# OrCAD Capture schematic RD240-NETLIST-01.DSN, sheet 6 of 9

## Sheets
6 4: size A3
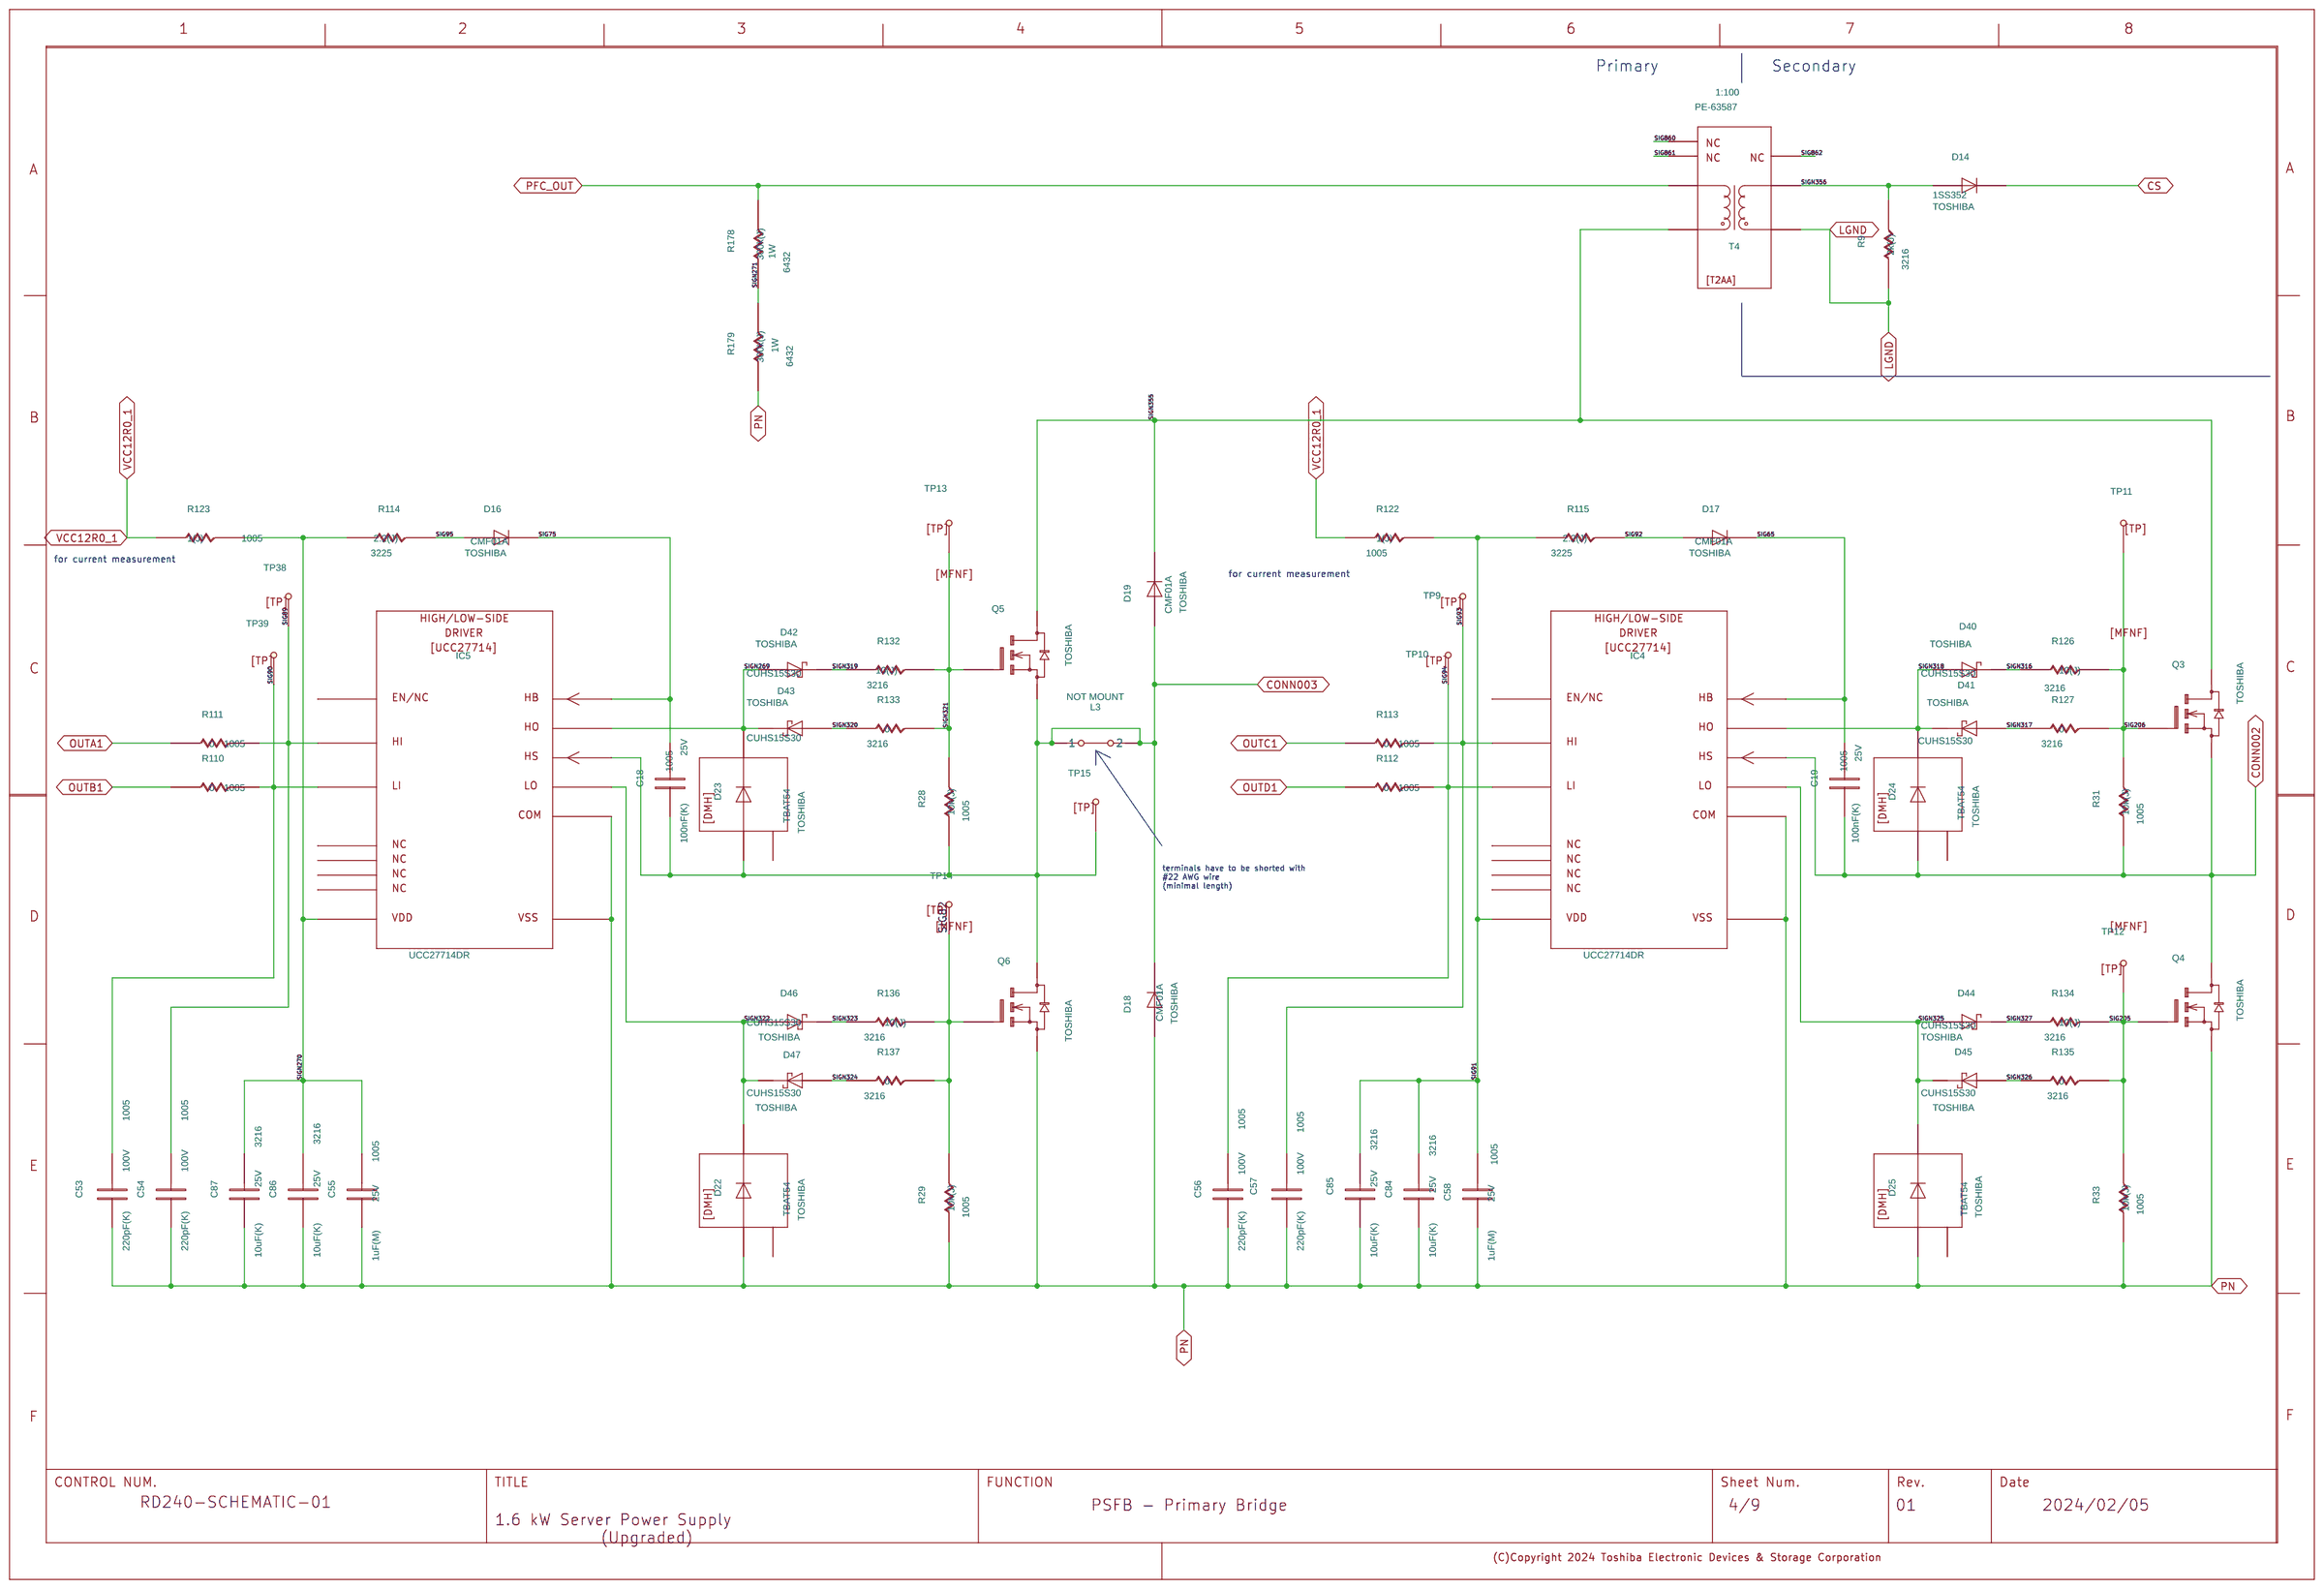
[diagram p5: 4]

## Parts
C18  C
C19  C
C53  C
C54  C
C55  C
C56  C
C57  C
C58  C
C84  C
C85  C
C86  C
C87  C
D14  D
D16  D
D17  D
D18  D
D19  D
D22  DMH
D23  DMH
D24  DMH
D25  DMH
D40  CUHS15S30
D41  CUHS15S30
D42  CUHS15S30
D43  CUHS15S30
D44  CUHS15S30
D45  CUHS15S30
D46  CUHS15S30
D47  CUHS15S30
IC4  L27714
IC5  L27714
L3  JP
Q3  TK095N65Z5
Q4  TK095N65Z5
Q5  TK095N65Z5
Q6  TK095N65Z5
R9  R
R28  R
R29  R
R31  R
R33  R
R110  R
R111  R
R112  R
R113  R
R114  R
R115  R
R122  R
R123  R
R126  R
R127  R
R132  R
R133  R
R134  R
R135  R
R136  R
R137  R
R178  R
R179  R
T4  T2AA
TP9  TP
TP10  TP
TP11  TP
TP12  TP
TP13  TP
TP14  TP
TP15  TP
TP38  TP
TP39  TP
U?#5  WAKU_DEF100

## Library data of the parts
C18 = C: ADSCNVFLAG: ON; ADSCOMPONENTNAME: C_1005; ADSMODELNAME: s_C1005JB1C224KT; AUTHOR: sptcae13; CAPACITANCETOLE: K; CDMASTERCADCELG: KC0005; CHIPSIZE: 1005; COMP: PRT_52; COMPONENTTYPE: 4; DATE: 2024/01/31; FNLEADFREETHET1GT2GMCTH1: N_N_N; GCOUNT: 1; ICX_PART_MODEL: CON_220N; INSTANCENAME: cmp63; MAKER: TDK; MAXGCOUNT: 1; NOMINALCAPACITA: 220n; OUMECLASSIFICATION: ƒZƒ‰ƒ~ƒbƒNƒRƒ“ƒfƒ“ƒT; OUMEMAKER: TDK ‚s‚c‚j; OUMEMAKERKATAMEI: C1005JB1C224KT; QUADMODEL: CON_220N; RATEDVOLTAGE: 16; SAVECOUNT: 0; SIZECODESMD: 1005; SQ_PART_MODEL: CON_220N; TEMPCHARACTERI2: B; TIME: 13:58:26; UPDATEDATE: 2024/01/31; UPDATETIME: 13:58:26; UPDATEUSER: sptcae13; VAL1: 100nF(K); VAL2: 25V; VAL3: C1005X7R1E104K050BB
C19 = C: ADSMODELNAME: s_C1005JB1C224KT; AUTHOR: sptcae13; CAPACITANCETOLE: K; CDMASTERCADCELG: KC0005; CHIPSIZE: 1005; COMP: PRT_52; COMPONENTTYPE: 4; DATE: 2024/01/31; FNLEADFREETHET1GT2GMCTH1: N_N_N; GCOUNT: 1; INSTANCENAME: cmp58; MAKER: TDK; MAXGCOUNT: 1; NOMINALCAPACITA: 220n; OUMECLASSIFICATION: ƒZƒ‰ƒ~ƒbƒNƒRƒ“ƒfƒ“ƒT; OUMEMAKER: TDK ‚s‚c‚j; OUMEMAKERKATAMEI: C1005JB1C224KT; QUADMODEL: CON_220N; RATEDVOLTAGE: 16; SAVECOUNT: 0; SIZECODESMD: 1005; TEMPCHARACTERI2: B; TIME: 13:58:26; UPDATEDATE: 2024/01/31; UPDATETIME: 13:58:26; UPDATEUSER: sptcae13; VAL1: 100nF(K); VAL2: 25V; VAL3: C1005X7R1E104K050BB
C53 = C: ADSMODELNAME: s_GRM155R61A225KE95D; AUTHOR: sptcae13; CAPACITANCETOLE: K; CDMASTERCADCELG: KC0005; CHIPSIZE: 1005; COMP: PRT_52; COMPONENTTYPE: 4; DATE: 2024/01/31; FNLEADFREETHET1GT2GMCTH1: N_N_N; GCOUNT: 1; INSTANCENAME: cmp165; MAKER: TDK; MAXGCOUNT: 1; NOMINALCAPACITA: 2.2u; OUMECLASSIFICATION: ƒZƒ‰ƒ~ƒbƒNƒRƒ“ƒfƒ“ƒT; OUMEMAKER: MRT ºc»ì; OUMEMAKERKATAMEI: GRM155R61A225KE95D; PMPRODUCTSTYPEG: HD1; QUADMODEL: CON_2.2U; RATEDVOLTAGE: 10; SAVECOUNT: 0; SIZECODESMD: 1005; TIME: 13:58:26; UPDATEDATE: 2024/01/31; UPDATETIME: 13:58:26; UPDATEUSER: sptcae13; VAL1: 220pF(K); VAL2: 100V; VAL3: GRM155R72A221KA01
C54 = C: ADSMODELNAME: s_GRM155R61A225KE95D; AUTHOR: sptcae13; CAPACITANCETOLE: K; CDMASTERCADCELG: KC0005; CHIPSIZE: 1005; COMP: PRT_52; COMPONENTTYPE: 4; DATE: 2024/01/31; FNLEADFREETHET1GT2GMCTH1: N_N_N; GCOUNT: 1; INSTANCENAME: cmp166; MAKER: TDK; MAXGCOUNT: 1; NOMINALCAPACITA: 2.2u; OUMECLASSIFICATION: ƒZƒ‰ƒ~ƒbƒNƒRƒ“ƒfƒ“ƒT; OUMEMAKER: MRT ºc»ì; OUMEMAKERKATAMEI: GRM155R61A225KE95D; PMPRODUCTSTYPEG: HD1; QUADMODEL: CON_2.2U; RATEDVOLTAGE: 10; SAVECOUNT: 0; SIZECODESMD: 1005; TIME: 13:58:26; UPDATEDATE: 2024/01/31; UPDATETIME: 13:58:26; UPDATEUSER: sptcae13; VAL1: 220pF(K); VAL2: 100V; VAL3: GRM155R72A221KA01
C55 = C: ADSCNVFLAG: ON; ADSCOMPONENTNAME: C_1005; ADSMODELNAME: s_GRM155R61A225KE95D; AUTHOR: sptcae13; CAPACITANCETOLE: K; CDMASTERCADCELG: KC0005; CHIPSIZE: 1005; COMP: PRT_52; COMPONENTTYPE: 4; DATE: 2024/01/31; FNLEADFREETHET1GT2GMCTH1: N_N_N; GCOUNT: 1; ICX_PART_MODEL: CON_2.2U; INSTANCENAME: cmp48; MAKER: TDK; MAXGCOUNT: 1; NOMINALCAPACITA: 2.2u; OUMECLASSIFICATION: ƒZƒ‰ƒ~ƒbƒNƒRƒ“ƒfƒ“ƒT; OUMEMAKER: MRT ºc»ì; OUMEMAKERKATAMEI: GRM155R61A225KE95D; PMPRODUCTSTYPEG: HD1; QUADMODEL: CON_2.2U; RATEDVOLTAGE: 10; SAVECOUNT: 0; SIZECODESMD: 1005; SQ_PART_MODEL: CON_2.2U; TIME: 13:58:26; UPDATEDATE: 2024/01/31; UPDATETIME: 13:58:26; UPDATEUSER: sptcae13; VAL1: 1uF(M); VAL2: 25V; VAL3: C1005X5R1E105M050BC
C56 = C: ADSMODELNAME: s_GRM155R61A225KE95D; AUTHOR: sptcae13; CAPACITANCETOLE: K; CDMASTERCADCELG: KC0005; CHIPSIZE: 1005; COMP: PRT_52; COMPONENTTYPE: 4; DATE: 2024/01/31; FNLEADFREETHET1GT2GMCTH1: N_N_N; GCOUNT: 1; INSTANCENAME: cmp163; MAKER: TDK; MAXGCOUNT: 1; NOMINALCAPACITA: 2.2u; OUMECLASSIFICATION: ƒZƒ‰ƒ~ƒbƒNƒRƒ“ƒfƒ“ƒT; OUMEMAKER: MRT ºc»ì; OUMEMAKERKATAMEI: GRM155R61A225KE95D; PMPRODUCTSTYPEG: HD1; QUADMODEL: CON_2.2U; RATEDVOLTAGE: 10; SAVECOUNT: 0; SIZECODESMD: 1005; TIME: 13:58:26; UPDATEDATE: 2024/01/31; UPDATETIME: 13:58:26; UPDATEUSER: sptcae13; VAL1: 220pF(K); VAL2: 100V; VAL3: GRM155R72A221KA01
C57 = C: ADSMODELNAME: s_GRM155R61A225KE95D; AUTHOR: sptcae13; CAPACITANCETOLE: K; CDMASTERCADCELG: KC0005; CHIPSIZE: 1005; COMP: PRT_52; COMPONENTTYPE: 4; DATE: 2024/01/31; FNLEADFREETHET1GT2GMCTH1: N_N_N; GCOUNT: 1; INSTANCENAME: cmp164; MAKER: TDK; MAXGCOUNT: 1; NOMINALCAPACITA: 2.2u; OUMECLASSIFICATION: ƒZƒ‰ƒ~ƒbƒNƒRƒ“ƒfƒ“ƒT; OUMEMAKER: MRT ºc»ì; OUMEMAKERKATAMEI: GRM155R61A225KE95D; PMPRODUCTSTYPEG: HD1; QUADMODEL: CON_2.2U; RATEDVOLTAGE: 10; SAVECOUNT: 0; SIZECODESMD: 1005; TIME: 13:58:26; UPDATEDATE: 2024/01/31; UPDATETIME: 13:58:26; UPDATEUSER: sptcae13; VAL1: 220pF(K); VAL2: 100V; VAL3: GRM155R72A221KA01
C58 = C: ADSMODELNAME: s_GRM155R61A225KE95D; AUTHOR: sptcae13; CAPACITANCETOLE: K; CDMASTERCADCELG: KC0005; CHIPSIZE: 1005; COMP: PRT_52; COMPONENTTYPE: 4; DATE: 2024/01/31; FNLEADFREETHET1GT2GMCTH1: N_N_N; GCOUNT: 1; INSTANCENAME: cmp49; MAKER: TDK; MAXGCOUNT: 1; NOMINALCAPACITA: 2.2u; OUMECLASSIFICATION: ƒZƒ‰ƒ~ƒbƒNƒRƒ“ƒfƒ“ƒT; OUMEMAKER: MRT ºc»ì; OUMEMAKERKATAMEI: GRM155R61A225KE95D; PMPRODUCTSTYPEG: HD1; QUADMODEL: CON_2.2U; RATEDVOLTAGE: 10; SAVECOUNT: 0; SIZECODESMD: 1005; TIME: 13:58:26; UPDATEDATE: 2024/01/31; UPDATETIME: 13:58:26; UPDATEUSER: sptcae13; VAL1: 1uF(M); VAL2: 25V; VAL3: C1005X5R1E105M050BC
C84 = C: ADSMODELNAME: s_TMK316LD106KL_T; AUTHOR: sptcae13; CAPACITANCETOLE: K; CDMASTERCADCELG: KC0014; CHIPSIZE: 3216; COMP: PRT_46; COMPONENTTYPE: 4; DATE: 2024/01/31; FNLEADFREETHET1GT2GMCTH1: N_N_N; GCOUNT: 1; INSTANCENAME: cmp138; MAKER: TAIYO YUDEN; MAXGCOUNT: 1; NOMINALCAPACITA: 10u; OUMECLASSIFICATION: ƒZƒ‰ƒ~ƒbƒNƒRƒ“ƒfƒ“ƒT; OUMEMAKER: TYD ‘¾—z—U“d; OUMEMAKERKATAMEI: TMK316LD106KL-T; QUADMODEL: CON_10U; RATEDVOLTAGE: 25; SAVECOUNT: 0; SIZECODESMD: 3216; TIME: 13:58:26; UPDATEDATE: 2024/01/31; UPDATETIME: 13:58:26; UPDATEUSER: sptcae13; VAL1: 10uF(K); VAL2: 25V; VAL3: TMK316BJ106KL-T
C85 = C: ADSMODELNAME: s_TMK316LD106KL_T; AUTHOR: sptcae13; CAPACITANCETOLE: K; CDMASTERCADCELG: KC0014; CHIPSIZE: 3216; COMP: PRT_46; COMPONENTTYPE: 4; DATE: 2024/01/31; FNLEADFREETHET1GT2GMCTH1: N_N_N; GCOUNT: 1; INSTANCENAME: cmp137; MAKER: TAIYO YUDEN; MAXGCOUNT: 1; NOMINALCAPACITA: 10u; OUMECLASSIFICATION: ƒZƒ‰ƒ~ƒbƒNƒRƒ“ƒfƒ“ƒT; OUMEMAKER: TYD ‘¾—z—U“d; OUMEMAKERKATAMEI: TMK316LD106KL-T; QUADMODEL: CON_10U; RATEDVOLTAGE: 25; SAVECOUNT: 0; SIZECODESMD: 3216; TIME: 13:58:26; UPDATEDATE: 2024/01/31; UPDATETIME: 13:58:26; UPDATEUSER: sptcae13; VAL1: 10uF(K); VAL2: 25V; VAL3: TMK316BJ106KL-T
C86 = C: ADSMODELNAME: s_TMK316LD106KL_T; AUTHOR: sptcae13; CAPACITANCETOLE: K; CDMASTERCADCELG: KC0014; CHIPSIZE: 3216; COMP: PRT_46; COMPONENTTYPE: 4; DATE: 2024/01/31; FNLEADFREETHET1GT2GMCTH1: N_N_N; GCOUNT: 1; INSTANCENAME: cmp150; MAKER: TAIYO YUDEN; MAXGCOUNT: 1; NOMINALCAPACITA: 10u; OUMECLASSIFICATION: ƒZƒ‰ƒ~ƒbƒNƒRƒ“ƒfƒ“ƒT; OUMEMAKER: TYD ‘¾—z—U“d; OUMEMAKERKATAMEI: TMK316LD106KL-T; QUADMODEL: CON_10U; RATEDVOLTAGE: 25; SAVECOUNT: 0; SIZECODESMD: 3216; TIME: 13:58:26; UPDATEDATE: 2024/01/31; UPDATETIME: 13:58:26; UPDATEUSER: sptcae13; VAL1: 10uF(K); VAL2: 25V; VAL3: TMK316BJ106KL-T
C87 = C: ADSMODELNAME: s_TMK316LD106KL_T; AUTHOR: sptcae13; CAPACITANCETOLE: K; CDMASTERCADCELG: KC0014; CHIPSIZE: 3216; COMP: PRT_46; COMPONENTTYPE: 4; DATE: 2024/01/31; FNLEADFREETHET1GT2GMCTH1: N_N_N; GCOUNT: 1; INSTANCENAME: cmp149; MAKER: TAIYO YUDEN; MAXGCOUNT: 1; NOMINALCAPACITA: 10u; OUMECLASSIFICATION: ƒZƒ‰ƒ~ƒbƒNƒRƒ“ƒfƒ“ƒT; OUMEMAKER: TYD ‘¾—z—U“d; OUMEMAKERKATAMEI: TMK316LD106KL-T; QUADMODEL: CON_10U; RATEDVOLTAGE: 25; SAVECOUNT: 0; SIZECODESMD: 3216; TIME: 13:58:26; UPDATEDATE: 2024/01/31; UPDATETIME: 13:58:26; UPDATEUSER: sptcae13; VAL1: 10uF(K); VAL2: 25V; VAL3: TMK316BJ106KL-T
D14 = D: ADSMODELNAME: s_1SS352_TPH3_F_1_1E1A; AUTHOR: sptcae13; CDMASTERCADCELG: D81022; COMP: PRT_27; COMPONENTTYPE: 4; DATE: 2024/01/31; FNLEADFREETHET1GT2GMCTH1: N_N_N; FORWARDVOLTAGEM: 0; GCOUNT: 1; INSTANCENAME: cmp66; MAKER: TOSHIBA; MAXAVERAGEFORWA: 0; MAXGCOUNT: 1; MAXREPETITIVEPE: 0; MAXREVERSEVOLTA: 80; MOUNTINGFORMSMD: SMD; OUMECLASSIFICATION: ¬M_CI[h; OUMEMAKER: TSB “ŒŽÅ; OUMEMAKERKATAMEI: 1SS352(TPH3,F)1-1E1A; PEAKFORWARDVOLT: 0; REVERSECURRENT: 0; TIME: 13:58:26; UPDATEDATE: 2024/01/31; UPDATETIME: 13:58:26; UPDATEUSER: sptcae13; USERCOMPTEXT3: TOSHIBA; VAL3: 1SS352; ZENERVOLTAGEMAX: 0; ZENERVOLTAGEMIN: 0
D16 = D: ADSMODELNAME: s_MURS220T3G; AUTHOR: sptcae13; CDMASTERCADCELG: DD924D; COMP: PRT_14; COMPONENTTYPE: 4; DATE: 2024/01/31; FNLEADFREETHET1GT2GMCTH1: 3_0_N; FORWARDVOLTAGEM: 0; GCOUNT: 1; INSTANCENAME: cmp30; MAKER: TOSHIBA; MAXAVERAGEFORWA: 2; MAXGCOUNT: 1; MAXREPETITIVEPE: 200; MAXREVERSEVOLTA: 0; MOUNTINGFORMSMD: SMD; OUMECLASSIFICATION: êÊ®¬fq; OUMEMAKER: ONS IZ~R_N^[; OUMEMAKERKATAMEI: MURS220T3G; PEAKFORWARDVOLT: 770m; PMPRODUCTSTYPEG: PJ1; REVERSECURRENT: 50u; TIME: 13:58:26; UPDATEDATE: 2024/01/31; UPDATETIME: 13:58:26; UPDATEUSER: sptcae13; USERCOMPTEXT3: TOSHIBA; VAL3: CMF01A; ZENERVOLTAGEMAX: 0; ZENERVOLTAGEMIN: 0
D17 = D: ADSMODELNAME: s_MURS220T3G; AUTHOR: sptcae13; CDMASTERCADCELG: DD924D; COMP: PRT_14; COMPONENTTYPE: 4; DATE: 2024/01/31; FNLEADFREETHET1GT2GMCTH1: 3_0_N; FORWARDVOLTAGEM: 0; GCOUNT: 1; INSTANCENAME: cmp5; MAKER: TOSHIBA; MAXAVERAGEFORWA: 2; MAXGCOUNT: 1; MAXREPETITIVEPE: 200; MAXREVERSEVOLTA: 0; MOUNTINGFORMSMD: SMD; OUMECLASSIFICATION: êÊ®¬fq; OUMEMAKER: ONS IZ~R_N^[; OUMEMAKERKATAMEI: MURS220T3G; PEAKFORWARDVOLT: 770m; PMPRODUCTSTYPEG: PJ1; REVERSECURRENT: 50u; TIME: 13:58:26; UPDATEDATE: 2024/01/31; UPDATETIME: 13:58:26; UPDATEUSER: sptcae13; USERCOMPTEXT3: TOSHIBA; VAL3: CMF01A; ZENERVOLTAGEMAX: 0; ZENERVOLTAGEMIN: 0
D18 = D: ADSMODELNAME: s_MURS340T3G@@; AUTHOR: sptcae13; CDMASTERCADCELG: KD0125; COMP: PRT_14; COMPONENTTYPE: 4; DATE: 2024/01/31; FNLEADFREETHET1GT2GMCTH1: N_N_N; FORWARDVOLTAGEM: 0; GCOUNT: 1; INSTANCENAME: cmp19; MAKER: TOSHIBA; MAXAVERAGEFORWA: 4; MAXGCOUNT: 1; MAXREPETITIVEPE: 400; MAXREVERSEVOLTA: 0; MOUNTINGFORMSMD: SMD; OUMECLASSIFICATION: êÊ®¬fq; OUMEMAKER: ONS IZ~R_N^[; OUMEMAKERKATAMEI: MURS340T3G@@; PEAKFORWARDVOLT: 1.28; PMPRODUCTSTYPEG: HEV; REVERSECURRENT: 250u; TIME: 13:58:26; UPDATEDATE: 2024/01/31; UPDATETIME: 13:58:26; UPDATEUSER: sptcae13; USERCOMPTEXT3: TOSHIBA; VAL3: CMF01A; ZENERVOLTAGEMAX: 0; ZENERVOLTAGEMIN: 0
D19 = D: ADSMODELNAME: s_MURS340T3G@@; AUTHOR: sptcae13; CDMASTERCADCELG: KD0125; COMP: PRT_14; COMPONENTTYPE: 4; DATE: 2024/01/31; FNLEADFREETHET1GT2GMCTH1: N_N_N; FORWARDVOLTAGEM: 0; GCOUNT: 1; INSTANCENAME: cmp18; MAKER: TOSHIBA; MAXAVERAGEFORWA: 4; MAXGCOUNT: 1; MAXREPETITIVEPE: 400; MAXREVERSEVOLTA: 0; MOUNTINGFORMSMD: SMD; OUMECLASSIFICATION: êÊ®¬fq; OUMEMAKER: ONS IZ~R_N^[; OUMEMAKERKATAMEI: MURS340T3G@@; PEAKFORWARDVOLT: 1.28; PMPRODUCTSTYPEG: HEV; REVERSECURRENT: 250u; TIME: 13:58:26; UPDATEDATE: 2024/01/31; UPDATETIME: 13:58:26; UPDATEUSER: sptcae13; USERCOMPTEXT3: TOSHIBA; VAL3: CMF01A; ZENERVOLTAGEMAX: 0; ZENERVOLTAGEMIN: 0
D22 = DMH: COMP: PRT_25; COMPONENTTYPE: 4; INSTANCENAME: cmp65; MAKER: TOSHIBA; USERCOMPTEXT3: TOSHIBA; VAL3: TBAT54
D23 = DMH: COMP: PRT_25; COMPONENTTYPE: 4; INSTANCENAME: cmp64; MAKER: TOSHIBA; USERCOMPTEXT3: TOSHIBA; VAL3: TBAT54
D24 = DMH: COMP: PRT_25; COMPONENTTYPE: 4; INSTANCENAME: cmp62; MAKER: TOSHIBA; USERCOMPTEXT3: TOSHIBA; VAL3: TBAT54
D25 = DMH: AUTHOR: sptcae13; COMP: PRT_25; COMPONENTTYPE: 4; DATE: 2024/01/31; INSTANCENAME: cmp60; MAKER: TOSHIBA; TIME: 13:58:25; UPDATEDATE: 2024/01/31; UPDATETIME: 13:58:25; UPDATEUSER: sptcae13; USERCOMPTEXT3: TOSHIBA; VAL3: TBAT54
D40 = CUHS15S30: COMPONENTTYPE: 4; INSTANCENAME: cmp111; MAKER: TOSHIBA; USERCOMPTEXT3: TOSHIBA
D41 = CUHS15S30: COMPONENTTYPE: 4; INSTANCENAME: cmp112; MAKER: TOSHIBA; USERCOMPTEXT3: TOSHIBA
D42 = CUHS15S30: COMPONENTTYPE: 4; INSTANCENAME: cmp115; MAKER: TOSHIBA; USERCOMPTEXT3: TOSHIBA
D43 = CUHS15S30: COMPONENTTYPE: 4; INSTANCENAME: cmp116; MAKER: TOSHIBA; USERCOMPTEXT3: TOSHIBA
D44 = CUHS15S30: COMPONENTTYPE: 4; INSTANCENAME: cmp113; MAKER: TOSHIBA; USERCOMPTEXT3: TOSHIBA
D45 = CUHS15S30: COMPONENTTYPE: 4; INSTANCENAME: cmp114; MAKER: TOSHIBA; USERCOMPTEXT3: TOSHIBA
D46 = CUHS15S30: COMPONENTTYPE: 4; INSTANCENAME: cmp117; MAKER: TOSHIBA; USERCOMPTEXT3: TOSHIBA
D47 = CUHS15S30: COMPONENTTYPE: 4; INSTANCENAME: cmp118; MAKER: TOSHIBA; USERCOMPTEXT3: TOSHIBA
IC4 = L27714: COMP: PRT_58; COMPONENTTYPE: 4; INSTANCENAME: cmp4; MAKER: TEXAS; VAL3: UCC27714DR
IC5 = L27714: COMP: PRT_58; COMPONENTTYPE: 4; INSTANCENAME: cmp20; MAKER: TEXAS; VAL3: UCC27714DR
L3 = JP: ADSMODELNAME: s_ERJ3GEY0R00V; AUTHOR: sptcae13; CDMASTERCADCELG: KC0008; COMP: PRT_64; COMPONENTTYPE: 4; DATE: 2024/01/31; FNLEADFREETHET1GT2GMCTH1: 2_1_N; GCOUNT: 1; INSTANCENAME: cmp130; MAXGCOUNT: 1; MOUNTINGFORMSMD: SMD; NOMINALRESISTAN: 0; NOTMOUNT: NOT MOUNT; OUMECLASSIFICATION: \ÊÀpÅèïRí; OUMEMAKER: NAE pi\jbNGNgjbNfoCX; OUMEMAKERKATAMEI: ERJ3GEY0R00V; OUMEPARTTYPE: R; PMPRODUCTSTYPEG: HD1-PC1; POWERRATING: 100m; QUADMODEL: RES_0; RESISTANCETOLER: X; SAVECOUNT: 0; TIME: 13:58:25; UPDATEDATE: 2024/01/31; UPDATETIME: 13:58:25; UPDATEUSER: sptcae13; VAL1: 0(X); VAL2: 100mW; VAL3: shortede by using 22AWG
Q3 = TK095N65Z5: COMPONENTTYPE: 4; INSTANCENAME: cmp12; MAKER: TOSHIBA; USERCOMPTEXT3: TOSHIBA
Q4 = TK095N65Z5: COMPONENTTYPE: 4; INSTANCENAME: cmp16; MAKER: TOSHIBA; USERCOMPTEXT3: TOSHIBA
Q5 = TK095N65Z5: COMPONENTTYPE: 4; INSTANCENAME: cmp28; MAKER: TOSHIBA; USERCOMPTEXT3: TOSHIBA
Q6 = TK095N65Z5: COMPONENTTYPE: 4; INSTANCENAME: cmp38; MAKER: TOSHIBA; USERCOMPTEXT3: TOSHIBA
R9 = R: ADSCNVFLAG: ON; ADSCOMPONENTNAME: R_3216; ADSMODELNAME: s_RK73H2BTTD4871F; CDMASTERCADCELG: DR901A; CHIPSIZE: 1608; COMPONENTTYPE: 4; FNLEADFREETHET1GT2GMCTH1: 3_1_N; GCOUNT: 1; ICX_PART_MODEL: RES_4.87K; INSTANCENAME: cmp39; MAKER: KOA; MAXGCOUNT: 1; MOUNTINGFORMSMD: SMD; NOMINALRESISTAN: 4.87K; OUMECLASSIFICATION: \ÊÀpÅèïRí; OUMEMAKER: KOA R[A; OUMEMAKERKATAMEI: RK73H2BTTD4871F; POWERRATING: 250m; QUADMODEL: RES_4.87K; RESISTANCETOLER: F; SAVECOUNT: 0; SIZECODESMD: 3216; VAL1: 2k(J); VAL2: 250mW; VAL3: RK73B2BTTD202J
R28 = R: ADSMODELNAME: s_RC0402FR_071KL; ALLGREEN: 0:O[; CDMASTERCADCELG: KC0005; CHIPSIZE: 1608; COMPONENTTYPE: 4; FNAPPROVALRESUG: B:i(GREEN); FNCANCELLATIONG: 0:Žg—p‰Â; FNENVIRONMANTRG: 1:gpL(K§ÎÛO); FNLEADFREETHET1GT2GMCTH1: 2_2_N; GANSWERREV: 8; GCOUNT: 1; INSTANCENAME: cmp25; MAKER: KOA; MAXGCOUNT: 1; MOUNTINGFORMSMD: SMD; NOMINALRESISTAN: 1K; OUMECLASSIFICATION: \ÊÀpÅèïRí; OUMEMAKER: YGO ƒ„ƒQƒI; OUMEMAKERKATAMEI: RC0402FR-071KL; PMPRODUCTSTYPEG: HD1; POWERRATING: 63m; QUADMODEL: RES_1K; RESISTANCETOLER: F; SAVECOUNT: 0; SIZECODESMD: 1005; VAL1: 10k(J); VAL2: 63mW; VAL3: RK73B1ERTTP103J
R29 = R: ADSMODELNAME: s_RC0402FR_071KL; ALLGREEN: 0:O[; CDMASTERCADCELG: KC0005; CHIPSIZE: 1608; COMPONENTTYPE: 4; FNAPPROVALRESUG: B:i(GREEN); FNCANCELLATIONG: 0:Žg—p‰Â; FNENVIRONMANTRG: 1:gpL(K§ÎÛO); FNLEADFREETHET1GT2GMCTH1: 2_2_N; GANSWERREV: 8; GCOUNT: 1; INSTANCENAME: cmp35; MAKER: KOA; MAXGCOUNT: 1; MOUNTINGFORMSMD: SMD; NOMINALRESISTAN: 1K; OUMECLASSIFICATION: \ÊÀpÅèïRí; OUMEMAKER: YGO ƒ„ƒQƒI; OUMEMAKERKATAMEI: RC0402FR-071KL; PMPRODUCTSTYPEG: HD1; POWERRATING: 63m; QUADMODEL: RES_1K; RESISTANCETOLER: F; SAVECOUNT: 0; SIZECODESMD: 1005; VAL1: 10k(J); VAL2: 63mW; VAL3: RK73B1ERTTP103J
R31 = R: ADSMODELNAME: s_RC0402FR_071KL; ALLGREEN: 0:O[; CDMASTERCADCELG: KC0005; CHIPSIZE: 1608; COMPONENTTYPE: 4; FNAPPROVALRESUG: B:i(GREEN); FNCANCELLATIONG: 0:Žg—p‰Â; FNENVIRONMANTRG: 1:gpL(K§ÎÛO); FNLEADFREETHET1GT2GMCTH1: 2_2_N; GANSWERREV: 8; GCOUNT: 1; INSTANCENAME: cmp11; MAKER: KOA; MAXGCOUNT: 1; MOUNTINGFORMSMD: SMD; NOMINALRESISTAN: 1K; OUMECLASSIFICATION: \ÊÀpÅèïRí; OUMEMAKER: YGO ƒ„ƒQƒI; OUMEMAKERKATAMEI: RC0402FR-071KL; PMPRODUCTSTYPEG: HD1; POWERRATING: 63m; QUADMODEL: RES_1K; RESISTANCETOLER: F; SAVECOUNT: 0; SIZECODESMD: 1005; VAL1: 10k(J); VAL2: 63mW; VAL3: RK73B1ERTTP103J
R33 = R: ADSMODELNAME: s_RC0402FR_071KL; ALLGREEN: 0:O[; CDMASTERCADCELG: KC0005; CHIPSIZE: 1608; COMPONENTTYPE: 4; FNAPPROVALRESUG: B:i(GREEN); FNCANCELLATIONG: 0:Žg—p‰Â; FNENVIRONMANTRG: 1:gpL(K§ÎÛO); FNLEADFREETHET1GT2GMCTH1: 2_2_N; GANSWERREV: 8; GCOUNT: 1; INSTANCENAME: cmp13; MAKER: KOA; MAXGCOUNT: 1; MOUNTINGFORMSMD: SMD; NOMINALRESISTAN: 1K; OUMECLASSIFICATION: \ÊÀpÅèïRí; OUMEMAKER: YGO ƒ„ƒQƒI; OUMEMAKERKATAMEI: RC0402FR-071KL; PMPRODUCTSTYPEG: HD1; POWERRATING: 63m; QUADMODEL: RES_1K; RESISTANCETOLER: F; SAVECOUNT: 0; SIZECODESMD: 1005; VAL1: 10k(J); VAL2: 63mW; VAL3: RK73B1ERTTP103J
R110 = R: ADSMODELNAME: s_RC0402FR_071KL; ALLGREEN: 0:O[; CDMASTERCADCELG: KC0005; CHIPSIZE: 1608; COMPONENTTYPE: 4; FNAPPROVALRESUG: B:i(GREEN); FNCANCELLATIONG: 0:Žg—p‰Â; FNENVIRONMANTRG: 1:gpL(K§ÎÛO); FNLEADFREETHET1GT2GMCTH1: 2_2_N; GANSWERREV: 8; GCOUNT: 1; INSTANCENAME: cmp144; MAKER: KOA; MAXGCOUNT: 1; MOUNTINGFORMSMD: SMD; NOMINALRESISTAN: 1K; OUMECLASSIFICATION: \ÊÀpÅèïRí; OUMEMAKER: YGO ƒ„ƒQƒI; OUMEMAKERKATAMEI: RC0402FR-071KL; PMPRODUCTSTYPEG: HD1; POWERRATING: 63m; QUADMODEL: RES_1K; RESISTANCETOLER: F; SAVECOUNT: 0; SIZECODESMD: 1005; VAL1: 0; VAL2: 63mW; VAL3: RK73Z1ETTP
R111 = R: ADSMODELNAME: s_RC0402FR_071KL; ALLGREEN: 0:O[; CDMASTERCADCELG: KC0005; CHIPSIZE: 1608; COMPONENTTYPE: 4; FNAPPROVALRESUG: B:i(GREEN); FNCANCELLATIONG: 0:Žg—p‰Â; FNENVIRONMANTRG: 1:gpL(K§ÎÛO); FNLEADFREETHET1GT2GMCTH1: 2_2_N; GANSWERREV: 8; GCOUNT: 1; INSTANCENAME: cmp145; MAKER: KOA; MAXGCOUNT: 1; MOUNTINGFORMSMD: SMD; NOMINALRESISTAN: 1K; OUMECLASSIFICATION: \ÊÀpÅèïRí; OUMEMAKER: YGO ƒ„ƒQƒI; OUMEMAKERKATAMEI: RC0402FR-071KL; PMPRODUCTSTYPEG: HD1; POWERRATING: 63m; QUADMODEL: RES_1K; RESISTANCETOLER: F; SAVECOUNT: 0; SIZECODESMD: 1005; VAL1: 0; VAL2: 63mW; VAL3: RK73Z1ETTP
R112 = R: ADSMODELNAME: s_RC0402FR_071KL; ALLGREEN: 0:O[; CDMASTERCADCELG: KC0005; CHIPSIZE: 1608; COMPONENTTYPE: 4; FNAPPROVALRESUG: B:i(GREEN); FNCANCELLATIONG: 0:Žg—p‰Â; FNENVIRONMANTRG: 1:gpL(K§ÎÛO); FNLEADFREETHET1GT2GMCTH1: 2_2_N; GANSWERREV: 8; GCOUNT: 1; INSTANCENAME: cmp134; MAKER: KOA; MAXGCOUNT: 1; MOUNTINGFORMSMD: SMD; NOMINALRESISTAN: 1K; OUMECLASSIFICATION: \ÊÀpÅèïRí; OUMEMAKER: YGO ƒ„ƒQƒI; OUMEMAKERKATAMEI: RC0402FR-071KL; PMPRODUCTSTYPEG: HD1; POWERRATING: 63m; QUADMODEL: RES_1K; RESISTANCETOLER: F; SAVECOUNT: 0; SIZECODESMD: 1005; VAL1: 0; VAL2: 63mW; VAL3: RK73Z1ETTP
R113 = R: ADSMODELNAME: s_RC0402FR_071KL; ALLGREEN: 0:O[; CDMASTERCADCELG: KC0005; CHIPSIZE: 1608; COMPONENTTYPE: 4; FNAPPROVALRESUG: B:i(GREEN); FNCANCELLATIONG: 0:Žg—p‰Â; FNENVIRONMANTRG: 1:gpL(K§ÎÛO); FNLEADFREETHET1GT2GMCTH1: 2_2_N; GANSWERREV: 8; GCOUNT: 1; INSTANCENAME: cmp133; MAKER: KOA; MAXGCOUNT: 1; MOUNTINGFORMSMD: SMD; NOMINALRESISTAN: 1K; OUMECLASSIFICATION: \ÊÀpÅèïRí; OUMEMAKER: YGO ƒ„ƒQƒI; OUMEMAKERKATAMEI: RC0402FR-071KL; PMPRODUCTSTYPEG: HD1; POWERRATING: 63m; QUADMODEL: RES_1K; RESISTANCETOLER: F; SAVECOUNT: 0; SIZECODESMD: 1005; VAL1: 0; VAL2: 63mW; VAL3: RK73Z1ETTP
R114 = R: ADSMODELNAME: s_RK73B2ETTD2R2J; CDMASTERCADCELG: DR903A; CHIPSIZE: 3225; COMPONENTTYPE: 4; FNLEADFREETHET1GT2GMCTH1: N_N_N; GCOUNT: 1; INSTANCENAME: cmp146; MAKER: PANASONIC; MAXGCOUNT: 1; MOUNTINGFORMSMD: SMD; NOMINALRESISTAN: 2.2; OUMECLASSIFICATION: \ÊÀpÅèïRí; OUMEMAKER: KOA R[A; OUMEMAKERKATAMEI: RK73B2ETTD2R2J; POWERRATING: 500m; QUADMODEL: RES_2.2; RESISTANCETOLER: J; SAVECOUNT: 0; SIZECODESMD: 3225; VAL1: 2.2(J); VAL2: 500mW; VAL3: ERJ-14YJ2R2U
R115 = R: ADSMODELNAME: s_SG73P2ETTD2R2J; CDMASTERCADCELG: KC0013; CHIPSIZE: 3225; COMPONENTTYPE: 4; FNLEADFREETHET1GT2GMCTH1: 3_0_N; GCOUNT: 1; INSTANCENAME: cmp132; MAKER: PANASONIC; MAXGCOUNT: 1; MOUNTINGFORMSMD: SMD; NOMINALRESISTAN: 2.2; OUMECLASSIFICATION: \ÊÀpÅèïRí; OUMEMAKER: KOA R[A; OUMEMAKERKATAMEI: SG73P2ETTD2R2J; PMPRODUCTSTYPEG: SV1; POWERRATING: 500m; QUADMODEL: RES_2.2; RESISTANCETOLER: J; SAVECOUNT: 0; SIZECODESMD: 3225; VAL1: 2.2(J); VAL2: 500mW; VAL3: ERJ-14YJ2R2U
R122 = R: ADSMODELNAME: s_RC0402FR_071KL; ALLGREEN: 0:O[; CDMASTERCADCELG: KC0005; CHIPSIZE: 1608; COMPONENTTYPE: 4; FNAPPROVALRESUG: B:i(GREEN); FNCANCELLATIONG: 0:Žg—p‰Â; FNENVIRONMANTRG: 1:gpL(K§ÎÛO); FNLEADFREETHET1GT2GMCTH1: 2_2_N; GANSWERREV: 8; GCOUNT: 1; INSTANCENAME: cmp131; MAKER: PANASONIC; MAXGCOUNT: 1; MOUNTINGFORMSMD: SMD; NOMINALRESISTAN: 1K; OUMECLASSIFICATION: \ÊÀpÅèïRí; OUMEMAKER: YGO ƒ„ƒQƒI; OUMEMAKERKATAMEI: RC0402FR-071KL; PMPRODUCTSTYPEG: HD1; POWERRATING: 63m; QUADMODEL: RES_1K; RESISTANCETOLER: F; SAVECOUNT: 0; SIZECODESMD: 1005; VAL1: 1(J); VAL2: 63mW; VAL3: ERJ2GEJ1R0X
R123 = R: ADSMODELNAME: s_RC0402FR_071KL; ALLGREEN: 0:O[; CDMASTERCADCELG: KC0005; CHIPSIZE: 1608; COMPONENTTYPE: 4; FNAPPROVALRESUG: B:i(GREEN); FNCANCELLATIONG: 0:Žg—p‰Â; FNENVIRONMANTRG: 1:gpL(K§ÎÛO); FNLEADFREETHET1GT2GMCTH1: 2_2_N; GANSWERREV: 8; GCOUNT: 1; INSTANCENAME: cmp143; MAKER: PANASONIC; MAXGCOUNT: 1; MOUNTINGFORMSMD: SMD; NOMINALRESISTAN: 1K; OUMECLASSIFICATION: \ÊÀpÅèïRí; OUMEMAKER: YGO ƒ„ƒQƒI; OUMEMAKERKATAMEI: RC0402FR-071KL; PMPRODUCTSTYPEG: HD1; POWERRATING: 63m; QUADMODEL: RES_1K; RESISTANCETOLER: F; SAVECOUNT: 0; SIZECODESMD: 1005; VAL1: 1(J); VAL2: 63mW; VAL3: ERJ2GEJ1R0X
R126 = R: ADSMODELNAME: s_RL1632H_R001_JN; CDMASTERCADCELG: KC0020; CHIPSIZE: 3216; COMPCOMMENT: ãÖFRK73B2BTTD100J; COMPONENTTYPE: 4; FNLEADFREETHET1GT2GMCTH1: N_N_N; GCOUNT: 1; INSTANCENAME: cmp139; MAKER: KOA; MAXGCOUNT: 1; MOUNTINGFORMSMD: SMD; NOMINALRESISTAN: 1m; OUMECLASSIFICATION: \ÊÀpÅèïRí; OUMEMAKER: SSM iHÆ; OUMEMAKERKATAMEI: RL1632H-R001-JN; POWERRATING: 500m; QUADMODEL: RES_1M; RESISTANCETOLER: J; SAVECOUNT: 0; SIZECODESMD: 3216; USERCOMPTEXT1: 10(J); VAL1: 10(J); VAL2: 250mW; VAL3: RK73B2BTTD100J
R127 = R: ADSMODELNAME: s_RL1632H_R001_JN; CDMASTERCADCELG: KC0020; CHIPSIZE: 3216; COMPONENTTYPE: 4; FNLEADFREETHET1GT2GMCTH1: N_N_N; GCOUNT: 1; INSTANCENAME: cmp140; MAKER: KOA; MAXGCOUNT: 1; MOUNTINGFORMSMD: SMD; NOMINALRESISTAN: 1m; OUMECLASSIFICATION: \ÊÀpÅèïRí; OUMEMAKER: SSM iHÆ; OUMEMAKERKATAMEI: RL1632H-R001-JN; POWERRATING: 500m; QUADMODEL: RES_1M; RESISTANCETOLER: J; SAVECOUNT: 0; SIZECODESMD: 3216; VAL1: 0; VAL2: 500mW; VAL3: RK73Z2BTTD
R132 = R: ADSMODELNAME: s_RL1632H_R001_JN; CDMASTERCADCELG: KC0020; CHIPSIZE: 3216; COMPCOMMENT: ãÖFRK73B2BTTD100J; COMPONENTTYPE: 4; FNLEADFREETHET1GT2GMCTH1: N_N_N; GCOUNT: 1; INSTANCENAME: cmp152; MAKER: KOA; MAXGCOUNT: 1; MOUNTINGFORMSMD: SMD; NOMINALRESISTAN: 1m; OUMECLASSIFICATION: \ÊÀpÅèïRí; OUMEMAKER: SSM iHÆ; OUMEMAKERKATAMEI: RL1632H-R001-JN; POWERRATING: 500m; QUADMODEL: RES_1M; RESISTANCETOLER: J; SAVECOUNT: 0; SIZECODESMD: 3216; USERCOMPTEXT1: 10(J); VAL1: 10(J); VAL2: 250mW; VAL3: RK73B2BTTD100J
R133 = R: ADSMODELNAME: s_RL1632H_R001_JN; CDMASTERCADCELG: KC0020; CHIPSIZE: 3216; COMPONENTTYPE: 4; FNLEADFREETHET1GT2GMCTH1: N_N_N; GCOUNT: 1; INSTANCENAME: cmp153; MAKER: KOA; MAXGCOUNT: 1; MOUNTINGFORMSMD: SMD; NOMINALRESISTAN: 1m; OUMECLASSIFICATION: \ÊÀpÅèïRí; OUMEMAKER: SSM iHÆ; OUMEMAKERKATAMEI: RL1632H-R001-JN; POWERRATING: 500m; QUADMODEL: RES_1M; RESISTANCETOLER: J; SAVECOUNT: 0; SIZECODESMD: 3216; VAL1: 0; VAL2: 500mW; VAL3: RK73Z2BTTD
R134 = R: ADSMODELNAME: s_RL1632H_R001_JN; CDMASTERCADCELG: KC0020; CHIPSIZE: 3216; COMPCOMMENT: ãÖFRK73B2BTTD100J; COMPONENTTYPE: 4; FNLEADFREETHET1GT2GMCTH1: N_N_N; GCOUNT: 1; INSTANCENAME: cmp141; MAKER: KOA; MAXGCOUNT: 1; MOUNTINGFORMSMD: SMD; NOMINALRESISTAN: 1m; OUMECLASSIFICATION: \ÊÀpÅèïRí; OUMEMAKER: SSM iHÆ; OUMEMAKERKATAMEI: RL1632H-R001-JN; POWERRATING: 500m; QUADMODEL: RES_1M; RESISTANCETOLER: J; SAVECOUNT: 0; SIZECODESMD: 3216; USERCOMPTEXT1: 10(J); VAL1: 10(J); VAL2: 250mW; VAL3: RK73B2BTTD100J
R135 = R: ADSMODELNAME: s_RL1632H_R001_JN; CDMASTERCADCELG: KC0020; CHIPSIZE: 3216; COMPONENTTYPE: 4; FNLEADFREETHET1GT2GMCTH1: N_N_N; GCOUNT: 1; INSTANCENAME: cmp142; MAKER: KOA; MAXGCOUNT: 1; MOUNTINGFORMSMD: SMD; NOMINALRESISTAN: 1m; OUMECLASSIFICATION: \ÊÀpÅèïRí; OUMEMAKER: SSM iHÆ; OUMEMAKERKATAMEI: RL1632H-R001-JN; POWERRATING: 500m; QUADMODEL: RES_1M; RESISTANCETOLER: J; SAVECOUNT: 0; SIZECODESMD: 3216; VAL1: 0; VAL2: 500mW; VAL3: RK73Z2BTTD
R136 = R: ADSMODELNAME: s_RL1632H_R001_JN; CDMASTERCADCELG: KC0020; CHIPSIZE: 3216; COMPCOMMENT: ãÖFRK73B2BTTD100J; COMPONENTTYPE: 4; FNLEADFREETHET1GT2GMCTH1: N_N_N; GCOUNT: 1; INSTANCENAME: cmp154; MAKER: KOA; MAXGCOUNT: 1; MOUNTINGFORMSMD: SMD; NOMINALRESISTAN: 1m; OUMECLASSIFICATION: \ÊÀpÅèïRí; OUMEMAKER: SSM iHÆ; OUMEMAKERKATAMEI: RL1632H-R001-JN; POWERRATING: 500m; QUADMODEL: RES_1M; RESISTANCETOLER: J; SAVECOUNT: 0; SIZECODESMD: 3216; USERCOMPTEXT1: 10(J); VAL1: 10(J); VAL2: 250mW; VAL3: RK73B2BTTD100J
R137 = R: ADSMODELNAME: s_RL1632H_R001_JN; CDMASTERCADCELG: KC0020; CHIPSIZE: 3216; COMPONENTTYPE: 4; FNLEADFREETHET1GT2GMCTH1: N_N_N; GCOUNT: 1; INSTANCENAME: cmp155; MAKER: KOA; MAXGCOUNT: 1; MOUNTINGFORMSMD: SMD; NOMINALRESISTAN: 1m; OUMECLASSIFICATION: \ÊÀpÅèïRí; OUMEMAKER: SSM iHÆ; OUMEMAKERKATAMEI: RL1632H-R001-JN; POWERRATING: 500m; QUADMODEL: RES_1M; RESISTANCETOLER: J; SAVECOUNT: 0; SIZECODESMD: 3216; VAL1: 0; VAL2: 500mW; VAL3: RK73Z2BTTD
R178 = R: CHIPSIZE: 6432; COMPONENTTYPE: 4; INSTANCENAME: cmp101; MAKER: VISHAY; SAVECOUNT: 0; SIZECODESMD: 6432; VAL1: 300k(J); VAL2: 1W; VAL3: CRCW2512300KJNEG
R179 = R: CHIPSIZE: 6432; COMPONENTTYPE: 4; INSTANCENAME: cmp102; MAKER: VISHAY; SAVECOUNT: 0; SIZECODESMD: 6432; VAL1: 300k(J); VAL2: 1W; VAL3: CRCW2512300KJNEG
T4 = T2AA: COMP: PRT_65; COMPONENTTYPE: 4; GCOUNT: 1; INDUCTANCEMAX: 0; INDUCTANCEMIN: 0; INSTANCENAME: cmp21; MAKER: PULSE; MAXGCOUNT: 1; MOUNTINGFORMSMD: DIP; NOMINALINDUCTA1: 140u; NOMINALINDUCTA2: X; VAL1: 1:100; VAL3: PE-63587
TP9 = TP: AUTHOR: sptcae13; COMP: PRT_44; COMPONENTTYPE: 4; DATE: 2024/01/31; INSTANCENAME: cmp119; MAKER: MAC8; TIME: 13:58:25; UPDATEDATE: 2024/01/31; UPDATETIME: 13:58:25; UPDATEUSER: sptcae13; VAL3: HK-2-S
TP10 = TP: AUTHOR: sptcae13; COMP: PRT_44; COMPONENTTYPE: 4; DATE: 2024/01/31; INSTANCENAME: cmp120; MAKER: MAC8; TIME: 13:58:25; UPDATEDATE: 2024/01/31; UPDATETIME: 13:58:25; UPDATEUSER: sptcae13; VAL3: HK-2-S
TP11 = TP: AUTHOR: sptcae13; COMP: PRT_44; COMPONENTTYPE: 4; DATE: 2024/01/31; INSTANCENAME: cmp121; MAKER: MAC8; TIME: 13:58:25; UPDATEDATE: 2024/01/31; UPDATETIME: 13:58:25; UPDATEUSER: sptcae13; VAL3: HK-2-S
TP12 = TP: AUTHOR: sptcae13; COMP: PRT_44; COMPONENTTYPE: 4; DATE: 2024/01/31; INSTANCENAME: cmp122; MAKER: MAC8; TIME: 13:58:25; UPDATEDATE: 2024/01/31; UPDATETIME: 13:58:25; UPDATEUSER: sptcae13; VAL3: HK-2-S
TP13 = TP: AUTHOR: sptcae13; COMP: PRT_44; COMPONENTTYPE: 4; DATE: 2024/01/31; INSTANCENAME: cmp124; MAKER: MAC8; TIME: 13:58:25; UPDATEDATE: 2024/01/31; UPDATETIME: 13:58:25; UPDATEUSER: sptcae13; VAL3: HK-2-S
TP14 = TP: AUTHOR: sptcae13; COMP: PRT_44; COMPONENTTYPE: 4; DATE: 2024/01/31; INSTANCENAME: cmp123; MAKER: MAC8; TIME: 13:58:25; UPDATEDATE: 2024/01/31; UPDATETIME: 13:58:25; UPDATEUSER: sptcae13; VAL3: HK-2-S
TP15 = TP: AUTHOR: sptcae13; COMP: PRT_44; COMPONENTTYPE: 4; DATE: 2024/01/31; INSTANCENAME: cmp125; MAKER: MAC8; TIME: 13:58:25; UPDATEDATE: 2024/01/31; UPDATETIME: 13:58:25; UPDATEUSER: sptcae13; VAL3: HK-2-S
TP38 = TP: AUTHOR: sptcae13; COMP: PRT_44; COMPONENTTYPE: 4; DATE: 2024/01/31; INSTANCENAME: cmp128; MAKER: MAC8; TIME: 13:58:25; UPDATEDATE: 2024/01/31; UPDATETIME: 13:58:25; UPDATEUSER: sptcae13; VAL3: HK-2-S
TP39 = TP: AUTHOR: sptcae13; COMP: PRT_44; COMPONENTTYPE: 4; DATE: 2024/01/31; INSTANCENAME: cmp127; MAKER: MAC8; TIME: 13:58:25; UPDATEDATE: 2024/01/31; UPDATETIME: 13:58:25; UPDATEUSER: sptcae13; VAL3: HK-2-S
U?#5 = WAKU_DEF100: COMPONENTTYPE: 2; DATE: 2024/02/05; DESIGNED: TOSHIBA; DRAWINGNUMBER: RD240-SCHEMATIC-01; FUNCTION: PSFB - Primary Bridge; INSTANCENAME: cmp157; PAGENUMBER: 4; REVISION: 01; SHEETNUMBER: 4/9; SHTSAVECOUNT: 43; TITLE: 1.6 kW Server Power Supply / (Upgraded); UPDATEDATE: 2024/02/07; UPDATETIME: 11:10:54; UPDATEUSER: t5459927

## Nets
VCC12R0_1: R122.1 R123.1 ; also on sheet 2 7 8 9
CONN002: C19.1 D24.A IC4.11 Q3.S Q4.D R31.1 ; also on sheet 5
CONN003: C18.1 D18.C D19.A D23.A IC5.11 L3.1(2) L3.2(1) Q5.S Q6.D R28.1 TP15.1 ; also on sheet 5
CS: D14.C ; also on sheet 4
LGND: R9.1 T4.3 ; also on sheet 1 2 3 4 5 9
OUTA1: R111.1 ; also on sheet 3
OUTB1: R110.1 ; also on sheet 3
OUTC1: R113.1 ; also on sheet 3
OUTD1: R112.1 ; also on sheet 3
PFC_OUT: R178.2 T4.2 ; also on sheet 2 7 8
PN: C53.1 C54.1 C55.1 C56.1 C57.1 C58.1 C84.1 C85.1 C86.1 C87.1 D18.A D22.A D25.A IC4.3 IC4.5 IC5.3 IC5.5 Q4.S Q6.S R29.1 R33.1 R179.1 ; also on sheet 2 3 7 8 9
SIG65: C19.2 D17.C IC4.13
SIG75: C18.2 D16.C IC5.13
SIG82: Q6.G R29.2 R136.2 R137.2 TP14.1
SIG89: C54.2 IC5.1 R111.2 TP38.1
SIG90: C53.2 IC5.2 R110.2 TP39.1
SIG91: C58.2 C84.2 C85.2 IC4.7 R115.1 R122.2
SIG92: D17.A R115.2
SIG93: C57.2 IC4.1 R113.2 TP9.1
SIG94: C56.2 IC4.2 R112.2 TP10.1
SIG95: D16.A R114.2
SIG205: Q4.G R33.2 R134.2 R135.2 TP12.1
SIG206: Q3.G R31.2 R126.2 R127.2 TP11.1
SIG860: T4.6
SIG861: T4.4
SIG862: T4.7
SIGN269: D23.C D42.A D43.C IC5.12
SIGN270: C55.2 C86.2 C87.2 IC5.7 R114.1 R123.2
SIGN271: R178.1 R179.2
SIGN316: D40.C R126.1
SIGN317: D41.A R127.1
SIGN318: D24.C D40.A D41.C IC4.12
SIGN319: D42.C R132.1
SIGN320: D43.A R133.1
SIGN321: Q5.G R28.2 R132.2 R133.2 TP13.1
SIGN322: D22.C D46.A D47.C IC5.6
SIGN323: D46.C R136.1
SIGN324: D47.A R137.1
SIGN325: D25.C D44.A D45.C IC4.6
SIGN326: D45.A R135.1
SIGN327: D44.C R134.1
SIGN355: D19.C Q3.D Q5.D T4.1
SIGN356: D14.A R9.2 T4.5

Not connected (* = marked no-connect by the designer): D22 NC; D23 NC; D24 NC; D25 NC; IC4 4 8 9 10 14; IC5 4 8 9 10 14

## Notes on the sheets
sheet 6
- Primary
- Secondary
- for current measurement
- for current measurement
- terminals have to be shorted with
  #22 AWG wire
  (minimal length)
